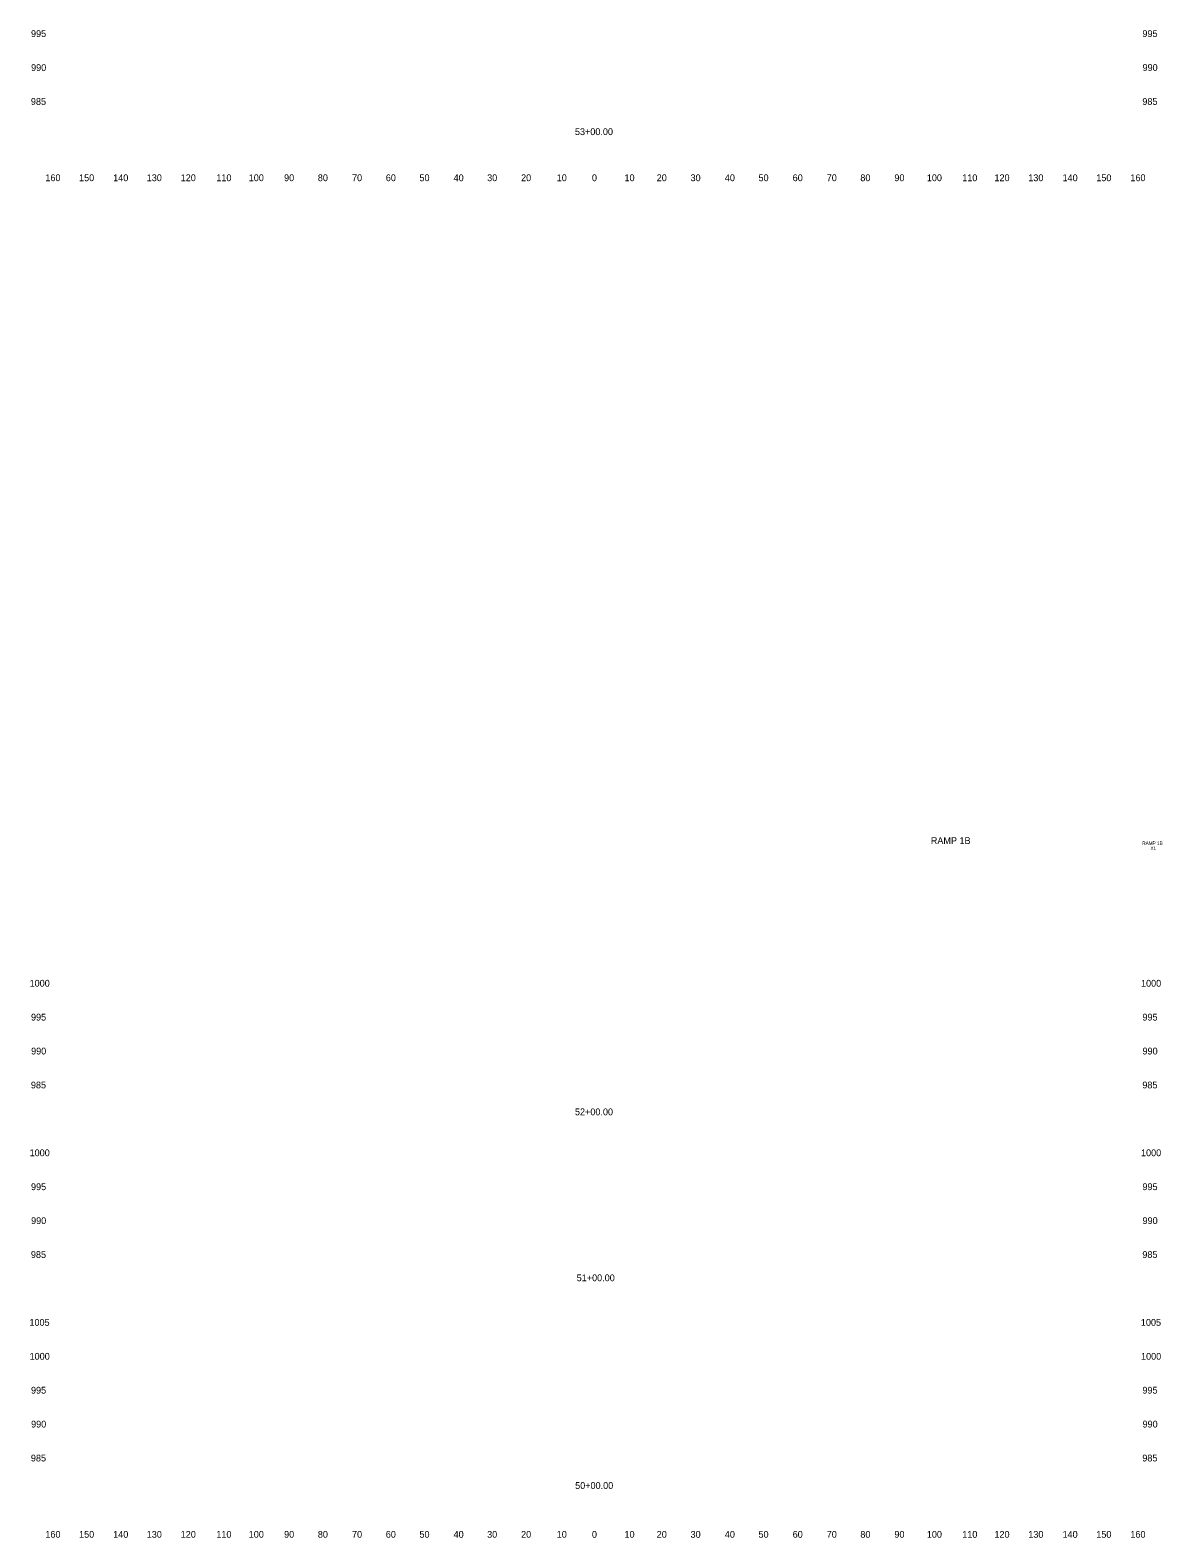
# Model space of a CAD drawing. Extents: x 4994 to 5843, y 4997 to 8804.
# Drawn here: x 4993.6 to 5327.4, y 4997.5 to 5442 of the extents above; entities that cross this region are included whole.
import ezdxf

# ---------------------------------------------------------------- set-up
doc = ezdxf.new("R2010")
doc.units = 0
for name, color, linetype in [('CLS_Search_Dist', 7, 'Continuous'), ('RD_XE_Ground', 7, 'Continuous'), ('UC_PD_Text', 7, 'Continuous')]:
    doc.layers.add(name, color=color, linetype=linetype)

msp = doc.modelspace()

# ---------------------------------------------------------------- texts
at = {"layer": 'CLS_Search_Dist'}
for s, p in [('995', (4993.86, 5440)), ('995', (5321.66, 5440)), ('990', (4993.89, 5430)), ('990', (5321.69, 5430)), ('985', (4993.83, 5420)), ('985', (5321.63, 5420)), ('160', (4998.1, 5397.5)), ('150', (5008.04, 5397.5)), ('140', (5018.1, 5397.5)), ('130', (5027.99, 5397.5)), ('120', (5038.01, 5397.5)), ('110', (5048.51, 5397.5)), ('100', (5058.07, 5397.5)), ('90', (5068.5, 5397.5)), ('80', (5078.46, 5397.5)), ('70', (5088.54, 5397.5)), ('60', (5098.5, 5397.5)), ('50', (5108.43, 5397.5)), ('40', (5118.5, 5397.5)), ('30', (5128.39, 5397.5)), ('20', (5138.4, 5397.5)), ('10', (5148.91, 5397.5)), ('0', (5159.3, 5397.5)), ('0', (5159.3, 5397.5)), ('10', (5168.91, 5397.5)), ('20', (5178.4, 5397.5)), ('30', (5188.39, 5397.5)), ('40', (5198.5, 5397.5)), ('50', (5208.43, 5397.5)), ('60', (5218.5, 5397.5)), ('70', (5228.54, 5397.5)), ('80', (5238.46, 5397.5)), ('90', (5248.5, 5397.5)), ('100', (5258.07, 5397.5)), ('110', (5268.51, 5397.5)), ('120', (5278.01, 5397.5)), ('130', (5287.99, 5397.5)), ('140', (5298.1, 5397.5)), ('150', (5308.04, 5397.5)), ('160', (5318.1, 5397.5)), ('1000', (4993.44, 5160)), ('1000', (5321.24, 5160)), ('995', (4993.86, 5150)), ('995', (5321.66, 5150)), ('990', (4993.89, 5140)), ('990', (5321.69, 5140)), ('985', (4993.83, 5130)), ('985', (5321.63, 5130)), ('1000', (4993.44, 5110)), ('1000', (5321.24, 5110)), ('995', (4993.86, 5100)), ('995', (5321.66, 5100)), ('990', (4993.89, 5090)), ('990', (5321.69, 5090)), ('985', (4993.83, 5080)), ('985', (5321.63, 5080)), ('1005', (4993.4, 5060)), ('1005', (5321.2, 5060)), ('1000', (4993.44, 5050)), ('1000', (5321.24, 5050)), ('995', (4993.86, 5040)), ('995', (5321.66, 5040)), ('990', (4993.89, 5030)), ('990', (5321.69, 5030)), ('985', (4993.83, 5020)), ('985', (5321.63, 5020)), ('160', (4998.1, 4997.5)), ('150', (5008.04, 4997.5)), ('140', (5018.1, 4997.5)), ('130', (5027.99, 4997.5)), ('120', (5038.01, 4997.5)), ('110', (5048.51, 4997.5)), ('100', (5058.07, 4997.5)), ('90', (5068.5, 4997.5)), ('80', (5078.46, 4997.5)), ('70', (5088.54, 4997.5)), ('60', (5098.5, 4997.5)), ('50', (5108.43, 4997.5)), ('40', (5118.5, 4997.5)), ('30', (5128.39, 4997.5)), ('20', (5138.4, 4997.5)), ('10', (5148.91, 4997.5)), ('0', (5159.3, 4997.5)), ('0', (5159.3, 4997.5)), ('10', (5168.91, 4997.5)), ('20', (5178.4, 4997.5)), ('30', (5188.39, 4997.5)), ('40', (5198.5, 4997.5)), ('50', (5208.43, 4997.5)), ('60', (5218.5, 4997.5)), ('70', (5228.54, 4997.5)), ('80', (5238.46, 4997.5)), ('90', (5248.5, 4997.5)), ('100', (5258.07, 4997.5)), ('110', (5268.51, 4997.5)), ('120', (5278.01, 4997.5)), ('130', (5287.99, 4997.5)), ('140', (5298.1, 4997.5)), ('150', (5308.04, 4997.5)), ('160', (5318.1, 4997.5))]:
    msp.add_text(s, height=2, dxfattribs=at).set_placement(p)
at = {"layer": 'RD_XE_Ground'}
for s, p in [('53+00.00', (5154.28, 5411.09)), ('52+00.00', (5154.29, 5122.08)), ('51+00.00', (5154.8, 5073.14)), ('50+00.00', (5154.35, 5011.9))]:
    msp.add_text(s, height=2, dxfattribs=at).set_placement(p)
at = {"layer": 'UC_PD_Text'}
for s, height, p in [('RAMP 1B', 2, (5259.24, 5202.06)), ('RAMP 1B', 1, (5321.59, 5201.8)), ('X1', 1, (5324.02, 5200.3))]:
    msp.add_text(s, height=height, dxfattribs=at).set_placement(p)

doc.saveas('drawing.dxf')
